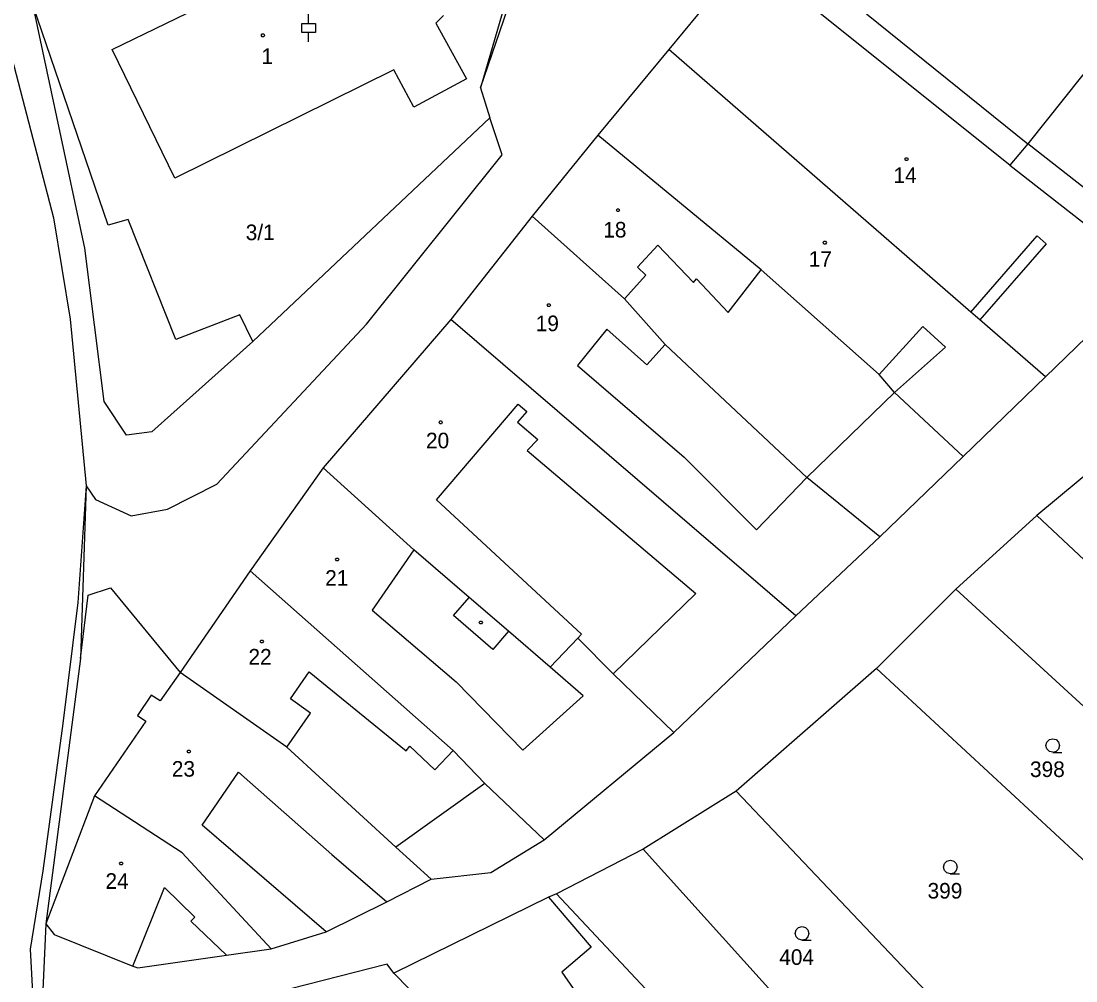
# Model space of a CAD drawing. Extents: x -609861 to -605046, y -1120287 to -1116307.
# Drawn here: x -607249.2 to -607134.3, y -1119345.6 to -1119241 of the extents above; entities that cross this region are included whole.
import ezdxf

# ---------------------------------------------------------------- set-up
doc = ezdxf.new("R2010")
doc.units = 0
for name, color, linetype in [('Vrstva 1', 7, 'Continuous'), ('Vrstva 2', 7, 'Continuous'), ('Vrstva 3', 7, 'Continuous'), ('Vrstva 4', 7, 'Continuous'), ('Vrstva 5', 7, 'Continuous')]:
    doc.layers.add(name, color=color, linetype=linetype)

msp = doc.modelspace()

# ---------------------------------------------------------------- linework, layer by layer
at = {"layer": 'Vrstva 1'}
for p, q in [((-607254.15, -1119229.94), (-607245.69, -1119262.4)), ((-607193.68, -1119229.43), (-607199.14, -1119248.22)), ((-607239.3, -1119244.04), (-607214.64, -1119232.11)), ((-607170.11, -1119233.73), (-607178.63, -1119244.06)), ((-607141.48, -1119256.68), (-607170.11, -1119233.73)), ((-607242.25, -1119265.72), (-607247.88, -1119239.31)), ((-607203.18, -1119240.36), (-607204.01, -1119241.19)), ((-607127.91, -1119239.73), (-607139.5, -1119254.33)), ((-607204.01, -1119241.19), (-607200.67, -1119247.25)), ((-607232.44, -1119258.08), (-607239.3, -1119244.04)), ((-607178.63, -1119244.06), (-607186.35, -1119253.4)), ((-607145.71, -1119272.68), (-607178.63, -1119244.06)), ((-607208.58, -1119246.27), (-607232.44, -1119258.08)), ((-607206.43, -1119250.34), (-607208.58, -1119246.27)), ((-607200.67, -1119247.25), (-607206.43, -1119250.34)), ((-607199.14, -1119248.22), (-607198.12, -1119251.5)), ((-607198.12, -1119251.5), (-607223.96, -1119275.89)), ((-607186.35, -1119253.4), (-607193.53, -1119262.22)), ((-607168.57, -1119268.09), (-607186.35, -1119253.4)), ((-607139.5, -1119254.33), (-607141.48, -1119256.68)), ((-607119.87, -1119269.81), (-607139.5, -1119254.33)), ((-607141.48, -1119256.68), (-607126.2, -1119268.6)), ((-607245.69, -1119262.4), (-607243.86, -1119273.44)), ((-607193.53, -1119262.22), (-607202.38, -1119273.48)), ((-607183.45, -1119271.23), (-607193.53, -1119262.22)), ((-607240.17, -1119282.44), (-607242.25, -1119265.72)), ((-607155.73, -1119279.48), (-607168.57, -1119268.09)), ((-607179.04, -1119276.2), (-607183.45, -1119271.23)), ((-607144.73, -1119273.53), (-607145.71, -1119272.68)), ((-607243.86, -1119273.44), (-607242.11, -1119291.63)), ((-607202.38, -1119273.48), (-607216.29, -1119289.66)), ((-607164.78, -1119305.79), (-607202.38, -1119273.48)), ((-607137.59, -1119279.73), (-607144.73, -1119273.53)), ((-607223.96, -1119275.89), (-607234.95, -1119285.72)), ((-607163.61, -1119290.72), (-607179.04, -1119276.2)), ((-607133.12, -1119275.43), (-607137.59, -1119279.73)), ((-607154.05, -1119281.44), (-607155.73, -1119279.48)), ((-607146.55, -1119288.41), (-607137.59, -1119279.73)), ((-607146.55, -1119288.41), (-607154.05, -1119281.44)), ((-607237.73, -1119286.11), (-607240.17, -1119282.44)), ((-607234.95, -1119285.72), (-607237.73, -1119286.11)), ((-607129.81, -1119287.56), (-607138.55, -1119294.86)), ((-607155.66, -1119297.19), (-607146.55, -1119288.41)), ((-607216.29, -1119289.66), (-607224.24, -1119300.9)), ((-607206.43, -1119298.59), (-607216.29, -1119289.66)), ((-607155.66, -1119297.19), (-607163.61, -1119290.72)), ((-607242.11, -1119291.63), (-607242.75, -1119310.45)), ((-607138.55, -1119294.86), (-607147.38, -1119302.89)), ((-607116.25, -1119315.74), (-607138.55, -1119294.86)), ((-607164.78, -1119305.79), (-607155.66, -1119297.19)), ((-607200.4, -1119303.78), (-607206.43, -1119298.59)), ((-607224.24, -1119300.9), (-607231.87, -1119311.98)), ((-607202.12, -1119320.48), (-607224.24, -1119300.9)), ((-607196.1, -1119307.47), (-607200.4, -1119303.78)), ((-607147.38, -1119302.89), (-607156.01, -1119311.54)), ((-607117.5, -1119330.31), (-607147.38, -1119302.89)), ((-607178.07, -1119318.5), (-607164.78, -1119305.79)), ((-607191.55, -1119311.39), (-607196.1, -1119307.47)), ((-607188.56, -1119308.23), (-607191.55, -1119311.39)), ((-607184.68, -1119312.12), (-607188.56, -1119308.23)), ((-607242.75, -1119310.45), (-607246.51, -1119339.38)), ((-607231.87, -1119311.98), (-607234.04, -1119315.05)), ((-607220.25, -1119320.09), (-607231.87, -1119311.98)), ((-607156.01, -1119311.54), (-607171.28, -1119324.89)), ((-607126.38, -1119338.96), (-607156.01, -1119311.54)), ((-607178.07, -1119318.5), (-607184.68, -1119312.12)), ((-607235.02, -1119314.45), (-607236.52, -1119316.64)), ((-607234.04, -1119315.05), (-607235.02, -1119314.45)), ((-607235.6, -1119317.27), (-607241.22, -1119325.42)), ((-607236.52, -1119316.64), (-607235.6, -1119317.27)), ((-607192.22, -1119330.22), (-607178.07, -1119318.5)), ((-607208.37, -1119331), (-607220.25, -1119320.09)), ((-607198.68, -1119324.06), (-607202.12, -1119320.48)), ((-607192.22, -1119330.22), (-607198.68, -1119324.06)), ((-607241.22, -1119325.42), (-607246.51, -1119339.38)), ((-607231.64, -1119331.63), (-607241.22, -1119325.42)), ((-607171.28, -1119324.89), (-607181.44, -1119331.24)), ((-607148.9, -1119348.51), (-607171.28, -1119324.89)), ((-607198.01, -1119333.76), (-607192.22, -1119330.22)), ((-607204.54, -1119334.51), (-607208.37, -1119331)), ((-607181.44, -1119331.24), (-607190.88, -1119336.1)), ((-607157.68, -1119357.56), (-607181.44, -1119331.24)), ((-607221.96, -1119342.08), (-607231.64, -1119331.63)), ((-607246.85, -1119333.59), (-607248.22, -1119342.14)), ((-607204.54, -1119334.51), (-607198.01, -1119333.76)), ((-607209.37, -1119336.97), (-607204.54, -1119334.51)), ((-607190.88, -1119336.1), (-607191.74, -1119336.44)), ((-607159.95, -1119369.02), (-607190.88, -1119336.1)), ((-607215.95, -1119340.22), (-607209.37, -1119336.97)), ((-607191.74, -1119336.44), (-607208.6, -1119344.73)), ((-607191.74, -1119336.44), (-607187.1, -1119341.89)), ((-607246.51, -1119339.38), (-607247.1, -1119352.04)), ((-607246.51, -1119339.38), (-607245.61, -1119340.54)), ((-607245.61, -1119340.54), (-607237.03, -1119343.97)), ((-607221.96, -1119342.08), (-607215.95, -1119340.22)), ((-607187.1, -1119341.89), (-607190.28, -1119344.64)), ((-607248.22, -1119342.14), (-607247.69, -1119352.36)), ((-607236.5, -1119344.15), (-607226.83, -1119342.77)), ((-607226.83, -1119342.77), (-607221.96, -1119342.08)), ((-607237.03, -1119343.97), (-607236.5, -1119344.15)), ((-607209.33, -1119343.76), (-607229.79, -1119348.96)), ((-607208.6, -1119344.73), (-607209.33, -1119343.76)), ((-607195.8, -1119357.81), (-607208.6, -1119344.73)), ((-607190.28, -1119344.64), (-607186.26, -1119350.44))]:
    msp.add_line(p, q, dxfattribs=at)
msp.add_lwpolyline([(-607242.11, -1119291.63), (-607243.04, -1119304.33), (-607244.66, -1119317.54), (-607246.85, -1119333.59)], dxfattribs=at)
at = {"layer": 'Vrstva 3'}
msp.add_line((-607217.88, -1119241.22), (-607217.88, -1119240.22), dxfattribs=at)
for points in [[(-607217.88, -1119243.22), (-607217.88, -1119242.22), (-607218.63, -1119242.22), (-607218.63, -1119241.22), (-607217.88, -1119241.22), (-607217.13, -1119241.22), (-607217.13, -1119242.22), (-607217.88, -1119242.22)], [(-607136.79, -1119320.66), (-607137.17, -1119320.56), (-607137.44, -1119320.29), (-607137.54, -1119319.92), (-607137.44, -1119319.55), (-607137.17, -1119319.28), (-607136.8, -1119319.18), (-607136.43, -1119319.28), (-607136.16, -1119319.55), (-607136.06, -1119319.93), (-607136.16, -1119320.31), (-607136.43, -1119320.58), (-607136.81, -1119320.68), (-607135.81, -1119320.68)], [(-607147.95, -1119333.91), (-607148.33, -1119333.81), (-607148.6, -1119333.54), (-607148.7, -1119333.17), (-607148.6, -1119332.8), (-607148.33, -1119332.53), (-607147.96, -1119332.43), (-607147.59, -1119332.53), (-607147.32, -1119332.8), (-607147.22, -1119333.18), (-607147.32, -1119333.56), (-607147.59, -1119333.83), (-607147.97, -1119333.93), (-607146.97, -1119333.93)], [(-607164.11, -1119341.14), (-607164.49, -1119341.04), (-607164.76, -1119340.77), (-607164.86, -1119340.4), (-607164.76, -1119340.03), (-607164.49, -1119339.76), (-607164.12, -1119339.66), (-607163.75, -1119339.76), (-607163.48, -1119340.03), (-607163.38, -1119340.41), (-607163.48, -1119340.79), (-607163.75, -1119341.06), (-607164.13, -1119341.16), (-607163.13, -1119341.16)]]:
    msp.add_lwpolyline(points, dxfattribs=at)
at = {"layer": 'Vrstva 4'}
for p, q in [((-607199.14, -1119248.22), (-607189.59, -1119220.34)), ((-607239.72, -1119263.21), (-607247.88, -1119239.31)), ((-607157.11, -1119240.17), (-607139.5, -1119254.33)), ((-607196.78, -1119255.54), (-607198.12, -1119251.5)), ((-607211.58, -1119273.98), (-607196.78, -1119255.54)), ((-607237.53, -1119262.57), (-607239.72, -1119263.21)), ((-607232.36, -1119275.66), (-607237.53, -1119262.57)), ((-607145.71, -1119272.68), (-607138.49, -1119264.38)), ((-607138.49, -1119264.38), (-607137.51, -1119265.23)), ((-607182.04, -1119267.78), (-607179.84, -1119265.39)), ((-607179.84, -1119265.39), (-607175.94, -1119269.44)), ((-607137.51, -1119265.23), (-607144.73, -1119273.53)), ((-607181.12, -1119268.65), (-607182.04, -1119267.78)), ((-607172.18, -1119272.71), (-607168.57, -1119268.09)), ((-607183.45, -1119271.23), (-607181.12, -1119268.65)), ((-607175.94, -1119269.44), (-607175.61, -1119269.06)), ((-607175.61, -1119269.06), (-607172.18, -1119272.71)), ((-607225.38, -1119272.98), (-607232.36, -1119275.66)), ((-607227.87, -1119291.44), (-607211.58, -1119273.98)), ((-607223.96, -1119275.89), (-607225.38, -1119272.98)), ((-607185.38, -1119274.56), (-607188.59, -1119278.5)), ((-607181.04, -1119278.44), (-607185.38, -1119274.56)), ((-607155.73, -1119279.48), (-607150.96, -1119274.24)), ((-607150.96, -1119274.24), (-607148.47, -1119276.52)), ((-607179.04, -1119276.2), (-607181.04, -1119278.44)), ((-607148.47, -1119276.52), (-607154.05, -1119281.44)), ((-607188.59, -1119278.5), (-607176.96, -1119288.49)), ((-607154.05, -1119281.44), (-607163.61, -1119290.72)), ((-607203.93, -1119293.15), (-607195.06, -1119282.7)), ((-607195.06, -1119282.7), (-607194.12, -1119283.5)), ((-607194.12, -1119283.5), (-607195.13, -1119284.69)), ((-607195.13, -1119284.69), (-607192.91, -1119286.56)), ((-607192.91, -1119286.56), (-607194.05, -1119287.78)), ((-607194.05, -1119287.78), (-607175.7, -1119303.36)), ((-607176.96, -1119288.49), (-607169.09, -1119296.42)), ((-607169.09, -1119296.42), (-607163.61, -1119290.72)), ((-607242.11, -1119291.63), (-607241.11, -1119293.11)), ((-607233.25, -1119294.16), (-607227.87, -1119291.44)), ((-607241.11, -1119293.11), (-607237.22, -1119294.88)), ((-607188.15, -1119307.8), (-607203.93, -1119293.15)), ((-607237.22, -1119294.88), (-607233.25, -1119294.16)), ((-607206.43, -1119298.59), (-607210.95, -1119305.17)), ((-607241.88, -1119303.53), (-607239.46, -1119302.73)), ((-607239.46, -1119302.73), (-607231.87, -1119311.98)), ((-607242.75, -1119310.45), (-607241.88, -1119303.53)), ((-607202.1, -1119305.75), (-607200.4, -1119303.78)), ((-607175.7, -1119303.36), (-607184.68, -1119312.12)), ((-607210.95, -1119305.17), (-607201.81, -1119312.98)), ((-607197.8, -1119309.46), (-607202.1, -1119305.75)), ((-607196.1, -1119307.47), (-607197.8, -1119309.46)), ((-607188.56, -1119308.23), (-607188.15, -1119307.8)), ((-607219.87, -1119314.85), (-607217.82, -1119311.9)), ((-607217.82, -1119311.9), (-607207.25, -1119320.5)), ((-607187.97, -1119314.52), (-607191.55, -1119311.39)), ((-607201.81, -1119312.98), (-607194.53, -1119320.42)), ((-607217.66, -1119316.4), (-607219.87, -1119314.85)), ((-607194.53, -1119320.42), (-607187.97, -1119314.52)), ((-607220.25, -1119320.09), (-607217.66, -1119316.4)), ((-607207.25, -1119320.5), (-607206.84, -1119320)), ((-607206.84, -1119320), (-607204.14, -1119322.59)), ((-607204.14, -1119322.59), (-607202.12, -1119320.48)), ((-607229.46, -1119328.61), (-607225.53, -1119322.84)), ((-607225.53, -1119322.84), (-607215.34, -1119331.79)), ((-607198.68, -1119324.06), (-607208.37, -1119331)), ((-607215.95, -1119340.22), (-607229.46, -1119328.61)), ((-607215.34, -1119331.79), (-607209.37, -1119336.97)), ((-607237.03, -1119343.97), (-607233.58, -1119335.41)), ((-607233.58, -1119335.41), (-607230.28, -1119338.62)), ((-607230.28, -1119338.62), (-607230.72, -1119339.07)), ((-607230.72, -1119339.07), (-607226.83, -1119342.77))]:
    msp.add_line(p, q, dxfattribs=at)
at = {"layer": 'Vrstva 5'}
for points in [[(-607222.77, -1119242.36), (-607222.68, -1119242.51), (-607222.77, -1119242.66), (-607222.95, -1119242.66), (-607223.04, -1119242.51), (-607222.95, -1119242.36)], [(-607152.64, -1119255.86), (-607152.55, -1119256.01), (-607152.64, -1119256.16), (-607152.82, -1119256.16), (-607152.91, -1119256.01), (-607152.82, -1119255.86)], [(-607184.08, -1119261.42), (-607183.99, -1119261.57), (-607184.08, -1119261.72), (-607184.26, -1119261.72), (-607184.35, -1119261.57), (-607184.26, -1119261.42)], [(-607161.55, -1119264.96), (-607161.46, -1119265.11), (-607161.55, -1119265.26), (-607161.73, -1119265.26), (-607161.82, -1119265.11), (-607161.73, -1119264.96)], [(-607191.6, -1119271.77), (-607191.51, -1119271.92), (-607191.6, -1119272.07), (-607191.78, -1119272.07), (-607191.87, -1119271.92), (-607191.78, -1119271.77)], [(-607203.4, -1119284.55), (-607203.31, -1119284.7), (-607203.4, -1119284.85), (-607203.58, -1119284.85), (-607203.67, -1119284.7), (-607203.58, -1119284.55)], [(-607214.67, -1119299.49), (-607214.58, -1119299.64), (-607214.67, -1119299.79), (-607214.85, -1119299.79), (-607214.94, -1119299.64), (-607214.85, -1119299.49)], [(-607199.04, -1119306.36), (-607198.95, -1119306.51), (-607199.04, -1119306.66), (-607199.22, -1119306.66), (-607199.31, -1119306.51), (-607199.22, -1119306.36)], [(-607222.89, -1119308.45), (-607222.8, -1119308.6), (-607222.89, -1119308.75), (-607223.07, -1119308.75), (-607223.16, -1119308.6), (-607223.07, -1119308.45)], [(-607230.83, -1119320.44), (-607230.74, -1119320.59), (-607230.83, -1119320.74), (-607231.01, -1119320.74), (-607231.1, -1119320.59), (-607231.01, -1119320.44)], [(-607238.2, -1119332.63), (-607238.11, -1119332.78), (-607238.2, -1119332.93), (-607238.38, -1119332.93), (-607238.47, -1119332.78), (-607238.38, -1119332.63)]]:
    msp.add_lwpolyline(points, close=True, dxfattribs=at)

# ---------------------------------------------------------------- texts
at = {"layer": 'Vrstva 2'}
for s, p in [('1', (-607223.017, -1119245.64)), ('14', (-607154.157, -1119258.61)), ('3/1', (-607224.733, -1119264.84)), ('18', (-607185.777, -1119264.55)), ('17', (-607163.387, -1119267.74)), ('19', (-607193.137, -1119274.76)), ('20', (-607205.093, -1119287.53)), ('21', (-607216.073, -1119302.51)), ('22', (-607224.433, -1119311.1)), ('23', (-607232.783, -1119323.32)), ('398', (-607139.283, -1119323.36)), ('24', (-607240.013, -1119335.55)), ('399', (-607150.443, -1119336.61)), ('404', (-607166.603, -1119343.84))]:
    msp.add_text(s, height=1.7, dxfattribs=at).set_placement(p)

doc.saveas('drawing.dxf')
